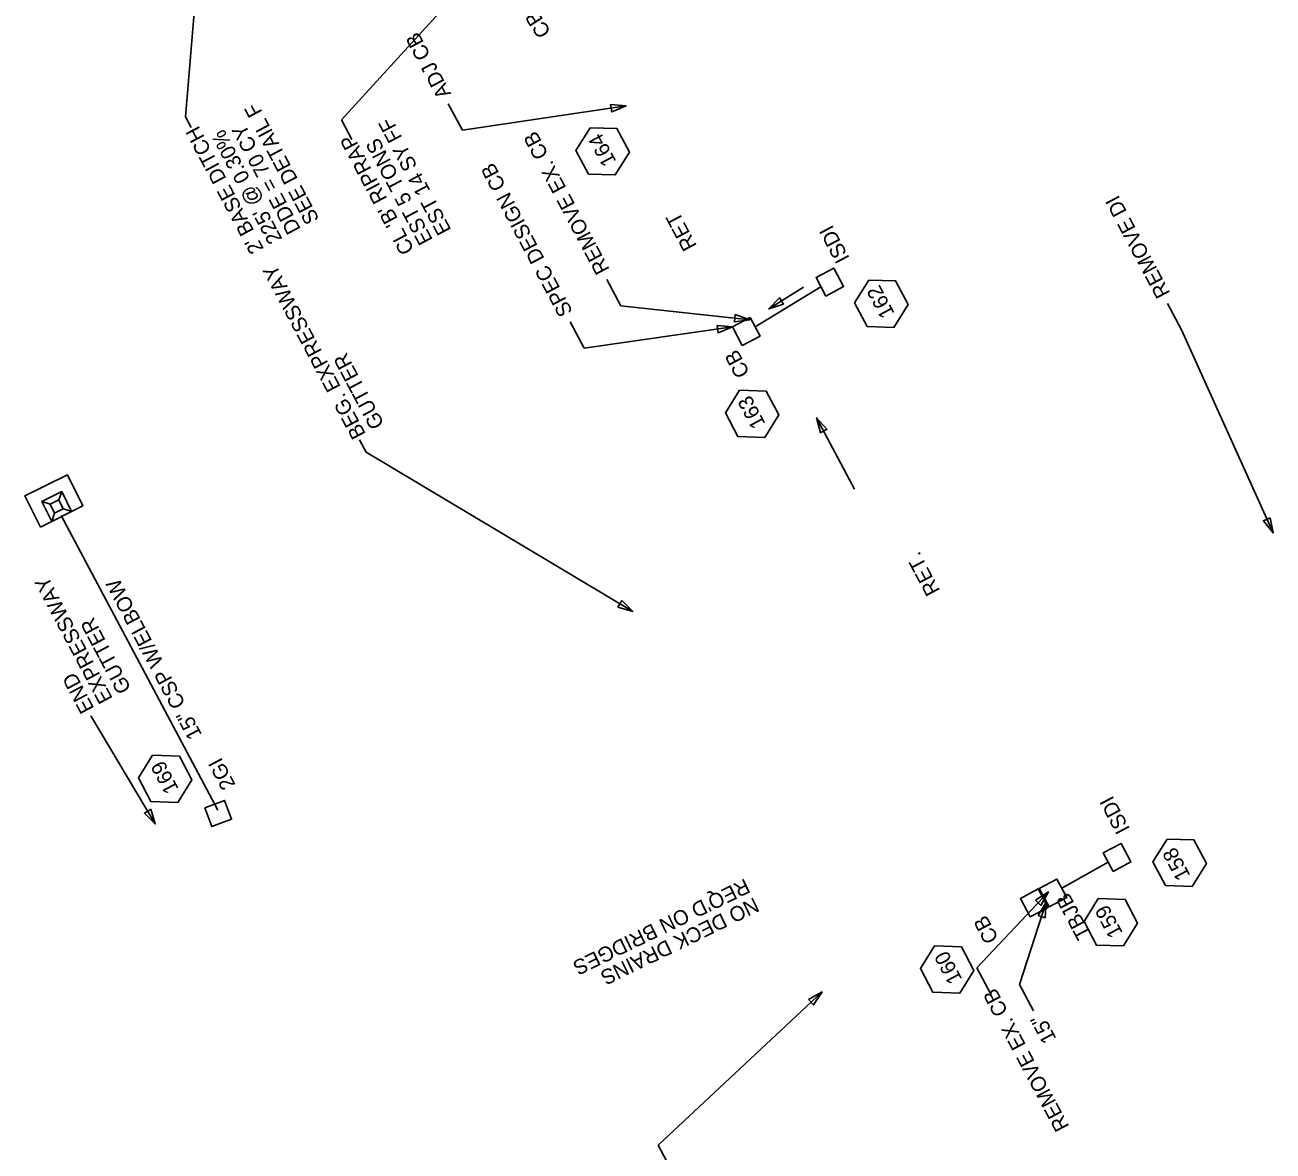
# Model space of a CAD drawing. Extents: x 2384780 to 2405432, y 547869 to 573706.
# Drawn here: x 2402170.8 to 2402587.8, y 570830.5 to 571206.6 of the extents above; entities that cross this region are included whole.
import ezdxf

# ---------------------------------------------------------------- set-up
doc = ezdxf.new("R2010")
doc.units = 0
for name, color, linetype in [('Old_Level_1', 7, 'Continuous'), ('Old_Level_20', 7, 'Continuous'), ('Old_Level_5', 7, 'Continuous'), ('Old_Level_9', 7, 'Continuous')]:
    doc.layers.add(name, color=color, linetype=linetype)

# ---------------------------------------------------------------- blocks, each defined once
blk = doc.blocks.new('PSS')
at = {"layer": 'Old_Level_1'}
for p, q in [((0, 14.8595), (0, 31.69675)), ((8.3065, 6.55325), (0, 14.8595)), ((21.4495, 6.591), (29.77475, 14.8595)), ((0, -31.71525), (0.00025, -14.859)), ((8.34375, -6.59075), (0.00025, -14.859)), ((21.46825, -6.55325), (29.77475, -14.8595))]:
    blk.add_line(p, q, dxfattribs=at)
for points in [[(0, 31.69675), (46.6125, 31.69675), (46.61225, -31.71575), (0, -31.71525)], [(0.00025, -14.859), (0, 14.8595)], [(0.00025, -14.859), (29.77475, -14.8595), (29.77475, 14.8595), (0, 14.8595)]]:
    blk.add_lwpolyline(points, dxfattribs=at)
blk.add_lwpolyline([(8.3065, 6.55325), (21.469, 6.553), (21.46825, -6.55325), (8.30625, -6.55325)], close=True, dxfattribs=at)

msp = doc.modelspace()

# ---------------------------------------------------------------- linework, layer by layer
at = {"layer": 'Old_Level_1'}
for p, q in [((2402436.78, 571119.21), (2402414.77, 571105.81)), ((2402235.28, 570944.36), (2402182.94, 571042.79)), ((2402532.76, 570927.05), (2402517.25, 570918.3)), ((2402512.77, 570917.08), (2402488.83, 570891.77)), ((2402512.05, 570913.62), (2402503.09, 570886.2)), ((2402493.52, 570882.94), (2402488.83, 570891.77)), ((2402507.78, 570877.37), (2402503.09, 570886.2))]:
    msp.add_line(p, q, dxfattribs=at)
for points in [[(2402230.92, 570945.19), (2402237.5, 570947.66), (2402239.86, 570941.38), (2402233.29, 570938.92)], [(2402534.41, 570923.94), (2402531.11, 570930.15), (2402537.04, 570933.3), (2402540.32, 570927.1)], [(2402512.98, 570912.05), (2402509.69, 570918.25), (2402515.61, 570921.4), (2402518.89, 570915.2)], [(2402506.73, 570908.72), (2402503.43, 570914.92), (2402509.36, 570918.08), (2402512.64, 570911.88)], [(2402508.42, 570914.31), (2402512.77, 570917.08), (2402510.24, 570912.59)], [(2402509.31, 570909.26), (2402512.05, 570913.62), (2402511.69, 570908.48)]]:
    msp.add_lwpolyline(points, close=True, dxfattribs=at)
at = {"layer": 'Old_Level_20'}
for points in [[(2402359.68, 571172.33), (2402354.94, 571164.74), (2402359.14, 571156.84), (2402368.08, 571156.53), (2402372.82, 571164.12), (2402368.62, 571172.02)], [(2402452.76, 571121.44), (2402448.02, 571113.85), (2402452.22, 571105.95), (2402461.16, 571105.64), (2402465.91, 571113.23), (2402461.7, 571121.13)], [(2402409.59, 571084.63), (2402404.84, 571077.05), (2402409.05, 571069.14), (2402417.99, 571068.83), (2402422.73, 571076.42), (2402418.53, 571084.32)], [(2402213.49, 570962.77), (2402208.74, 570955.18), (2402212.94, 570947.28), (2402221.89, 570946.97), (2402226.63, 570954.56), (2402222.43, 570962.46)], [(2402552.44, 570934.74), (2402547.7, 570927.15), (2402551.9, 570919.25), (2402560.85, 570918.94), (2402565.59, 570926.53), (2402561.39, 570934.43)], [(2402529.42, 570914.84), (2402524.68, 570907.26), (2402528.88, 570899.35), (2402537.82, 570899.04), (2402542.57, 570906.63), (2402538.37, 570914.53)], [(2402474.75, 570899.06), (2402470.01, 570891.47), (2402474.21, 570883.57), (2402483.16, 570883.26), (2402487.9, 570890.84), (2402483.7, 570898.75)]]:
    msp.add_lwpolyline(points, close=True, dxfattribs=at)
at = {"layer": 'Old_Level_5'}
for p, q in [((2402229.06, 571231.59), (2402224.52, 571175.91)), ((2402314.66, 571216.65), (2402276.58, 571174.97)), ((2402312.27, 571180.29), (2402316.97, 571171.46)), ((2402371.65, 571179.59), (2402316.97, 571171.46)), ((2402224.52, 571175.91), (2402226.38, 571172.4)), ((2402276.58, 571174.97), (2402280.1, 571168.35)), ((2402365.26, 571121.6), (2402369.95, 571112.78)), ((2402419.35, 571111.78), (2402430.91, 571119.09)), ((2402412.98, 571108.17), (2402369.95, 571112.78)), ((2402552.56, 571113.66), (2402557.25, 571104.83)), ((2402352.94, 571107.47), (2402357.63, 571098.64)), ((2402407.2, 571105.77), (2402357.63, 571098.64)), ((2402587.83, 571037), (2402557.25, 571104.83)), ((2402435.34, 571075.45), (2402448.04, 571051.56)), ((2402282.6, 571068.05), (2402284.79, 571063.93)), ((2402373.9, 571010.75), (2402284.79, 571063.93)), ((2402214.37, 570939.78), (2402192.9, 570975.93)), ((2402437.14, 570883.67), (2402382.35, 570832.49)), ((2402387.04, 570823.66), (2402382.35, 570832.49))]:
    msp.add_line(p, q, dxfattribs=at)
for points in [[(2402366.52, 571180.09), (2402371.65, 571179.59), (2402366.89, 571177.62)], [(2402424.24, 571113.39), (2402419.35, 571111.78), (2402422.91, 571115.51)], [(2402408.14, 571109.94), (2402412.98, 571108.17), (2402407.88, 571107.46)], [(2402402.08, 571106.29), (2402407.2, 571105.77), (2402402.43, 571103.82)], [(2402436.58, 571070.45), (2402435.34, 571075.45), (2402438.79, 571071.62)], [(2402586.91, 571042.08), (2402587.83, 571037), (2402584.63, 571041.05)], [(2402370.24, 571014.39), (2402373.9, 571010.75), (2402368.96, 571012.24)], [(2402212.89, 570944.71), (2402214.37, 570939.78), (2402210.74, 570943.44)], [(2402432.63, 570881.17), (2402437.14, 570883.67), (2402434.34, 570879.35)]]:
    msp.add_lwpolyline(points, close=True, dxfattribs=at)
at = {"layer": 'Old_Level_9'}
for points in [[(2402438.43, 571116.11), (2402435.13, 571122.31), (2402441.04, 571125.46), (2402444.34, 571119.26)], [(2402410.5, 571099.56), (2402407.2, 571105.77), (2402413.12, 571108.91), (2402416.42, 571102.71)]]:
    msp.add_lwpolyline(points, close=True, dxfattribs=at)

# ---------------------------------------------------------------- block references
at = {"layer": 'Old_Level_5', "xscale": 0.24999999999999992, "yscale": 0.24999999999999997, "rotation": 116.34237094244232}
msp.add_blockref('PSS', (2402183.11, 571042.48), dxfattribs=at)

# ---------------------------------------------------------------- texts
at = {"layer": 'Old_Level_1'}
for s, rotation, p in [('RET.', 117.9999, (2402476.68, 571017.68)), ('ISDI', 117.9999, (2402540.16, 570938.11)), ("REQ'D ON BRIDGES", 205.8788, (2402411.43, 570921.7)), ('NO DECK DRAINS', 205.8788, (2402414.48, 570915.4)), ('TBJB', 117.9999, (2402527.12, 570902.82)), ('CB', 117.9999, (2402496.25, 570901.49)), ('REMOVE EX. CB', 117.9999, (2402519.85, 570838.74)), ('15"', 117.9999, (2402515.55, 570868.09))]:
    msp.add_text(s, height=5, rotation=rotation, dxfattribs=at).set_placement(p)
at = {"layer": 'Old_Level_20'}
for s, p in [('164', (2402368.51, 571161.05)), ('162', (2402461.51, 571110.31)), ('163', (2402418.38, 571073.43)), ('169', (2402222.3, 570951.52)), ('158', (2402560.31, 570922.55)), ('159', (2402537.74, 570903.39)), ('160', (2402484.09, 570887.96))]:
    msp.add_text(s, height=5, rotation=117.9999, dxfattribs=at).set_placement(p)
at = {"layer": 'Old_Level_5'}
for s, rotation, p in [('CB', 123.2009, (2402346.77, 571204.35)), ('ADJ CB', 117.9999, (2402313.31, 571183.67)), ('SEE DETAIL F', 117.9999, (2402269.29, 571141.7)), ('EST 14 SY FF', 117.9999, (2402313.39, 571138.15)), ("2' BASE DITCH", 117.9999, (2402250.75, 571131.84)), ("225' @ 0.30%", 117.9999, (2402256.93, 571135.13)), ('DDE = 70 CY', 117.9999, (2402263.11, 571138.41)), ('REMOVE EX. CB', 117.9999, (2402366.29, 571124.99)), ("CL 'B' RIPRAP", 117.9999, (2402301.03, 571131.57)), ('EST 5 TONS', 117.9999, (2402307.21, 571134.86)), ('SPEC DESIGN CB', 117.9999, (2402353.97, 571110.85)), ('REMOVE DI', 117.9999, (2402553.59, 571117.04)), ('RET', 117.9999, (2402395.43, 571132.86)), ('ISDI', 117.9999, (2402446.48, 571128.74)), ('BEG. EXPRESSWAY', 118, (2402284.83, 571070)), ('GUTTER', 118, (2402291.01, 571073.29)), ('CB', 117.9999, (2402413.11, 571090.43)), ('EXPRESSWAY', 117.9999, (2402200.28, 570981.66)), ('15" CSP W/ELBOW', 117.9999, (2402230.1, 570969.6)), ('GUTTER', 117.9999, (2402206.46, 570984.94)), ('END', 117.9999, (2402194.1, 570978.37)), ('2GI', 117.9999, (2402241.31, 570952.84))]:
    msp.add_text(s, height=5, rotation=rotation, dxfattribs=at).set_placement(p)

doc.saveas('drawing.dxf')
